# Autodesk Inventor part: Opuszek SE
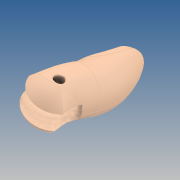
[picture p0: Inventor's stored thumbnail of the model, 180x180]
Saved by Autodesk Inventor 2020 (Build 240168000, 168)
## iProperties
Created: 2019-10
Part Number: Opuszek SE
Material: GFRP
Document SubType Name: Modeling
Designer: yello
Density: 1.75 g/cm^3
Appearance: Default
Author: yello
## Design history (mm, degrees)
feature "Opuszek SE"
sketch "Sketch1"
  geometry: C1 r 2 at (0, 0); 1 further point
  constraints: 1 centre point
  dimensions: "d0" = 4 diameter of C1
extrude "Extrusion1" cut sketch "Sketch1" stored distance "d1" = 100; taper "d2" = 0 deg
body "Solid1"
